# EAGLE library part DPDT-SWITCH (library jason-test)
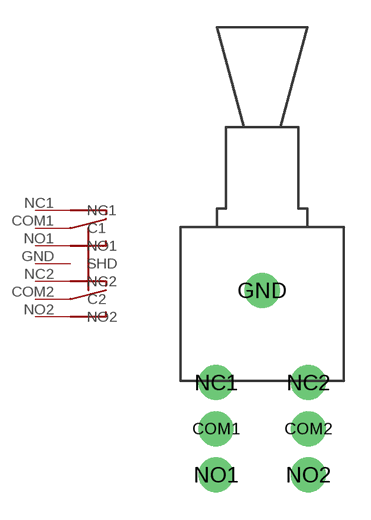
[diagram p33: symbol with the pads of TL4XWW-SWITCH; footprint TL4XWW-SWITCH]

Designator prefix -

## DPDT-SWITCHTL4XWW  [TL4XWW-SWITCH]
COM1  C1
COM2  C2
GND  SHD  pwr
NC1  NC1
NC2  NC2
NO1  NO1
NO2  NO2

## Footprint TL4XWW-SWITCH (pad centres in mm)
drill 1.1 pad 1.93 round: COM1 -2.54,-7.62; COM2 2.54,-7.62; GND 0,0; NC1 -2.54,-5.08; NC2 2.54,-5.08; NO1 -2.54,-10.16; NO2 2.54,-10.16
